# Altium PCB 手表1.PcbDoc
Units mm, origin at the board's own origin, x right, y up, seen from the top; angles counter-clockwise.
Board outline 35.6 x 38.85 mm, 2 copper layers (Top Layer, Bottom Layer); 53 components, 41 nets, 221 pads, 136 vias.
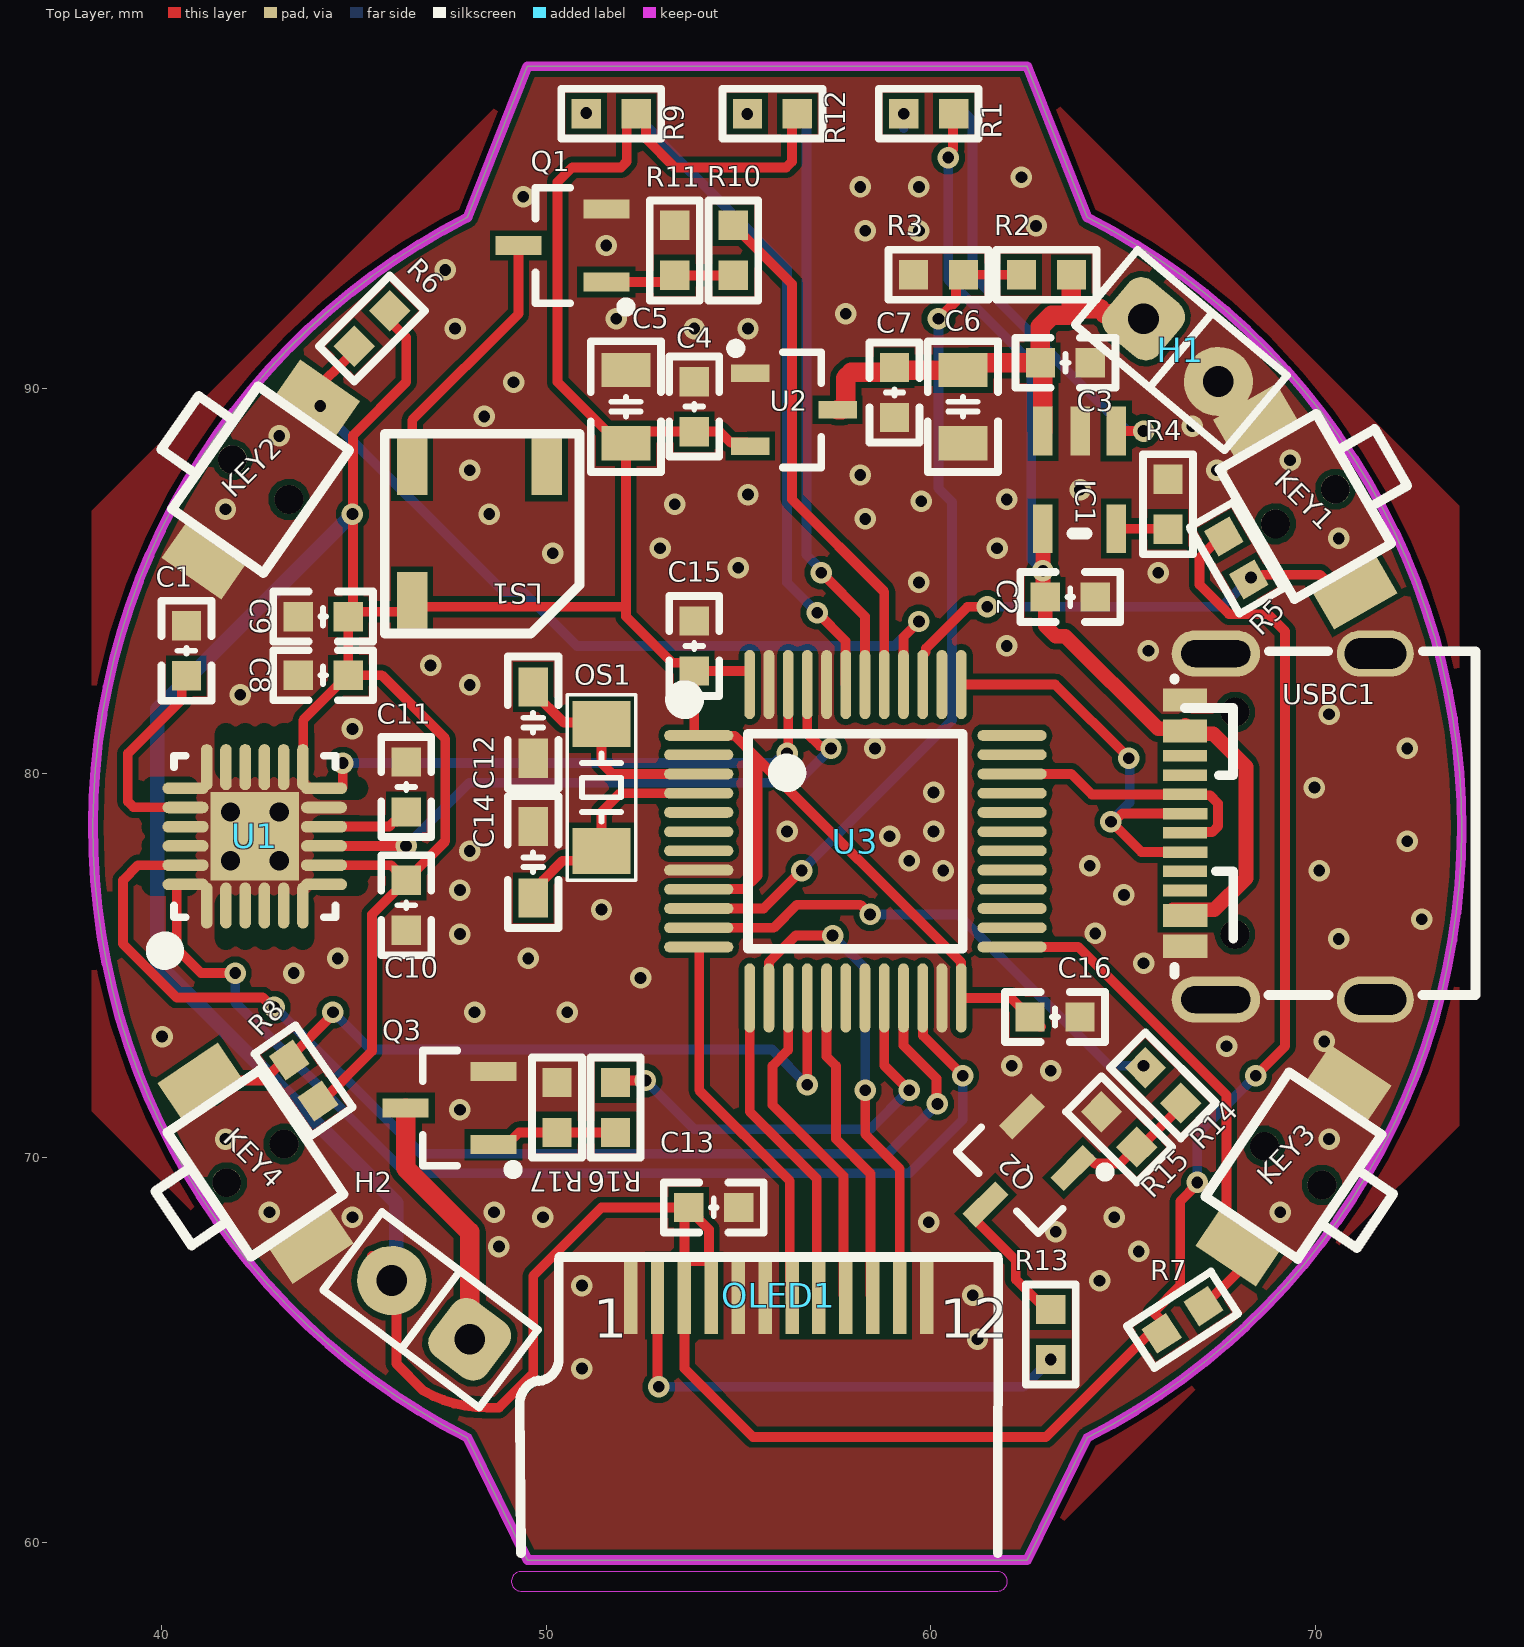
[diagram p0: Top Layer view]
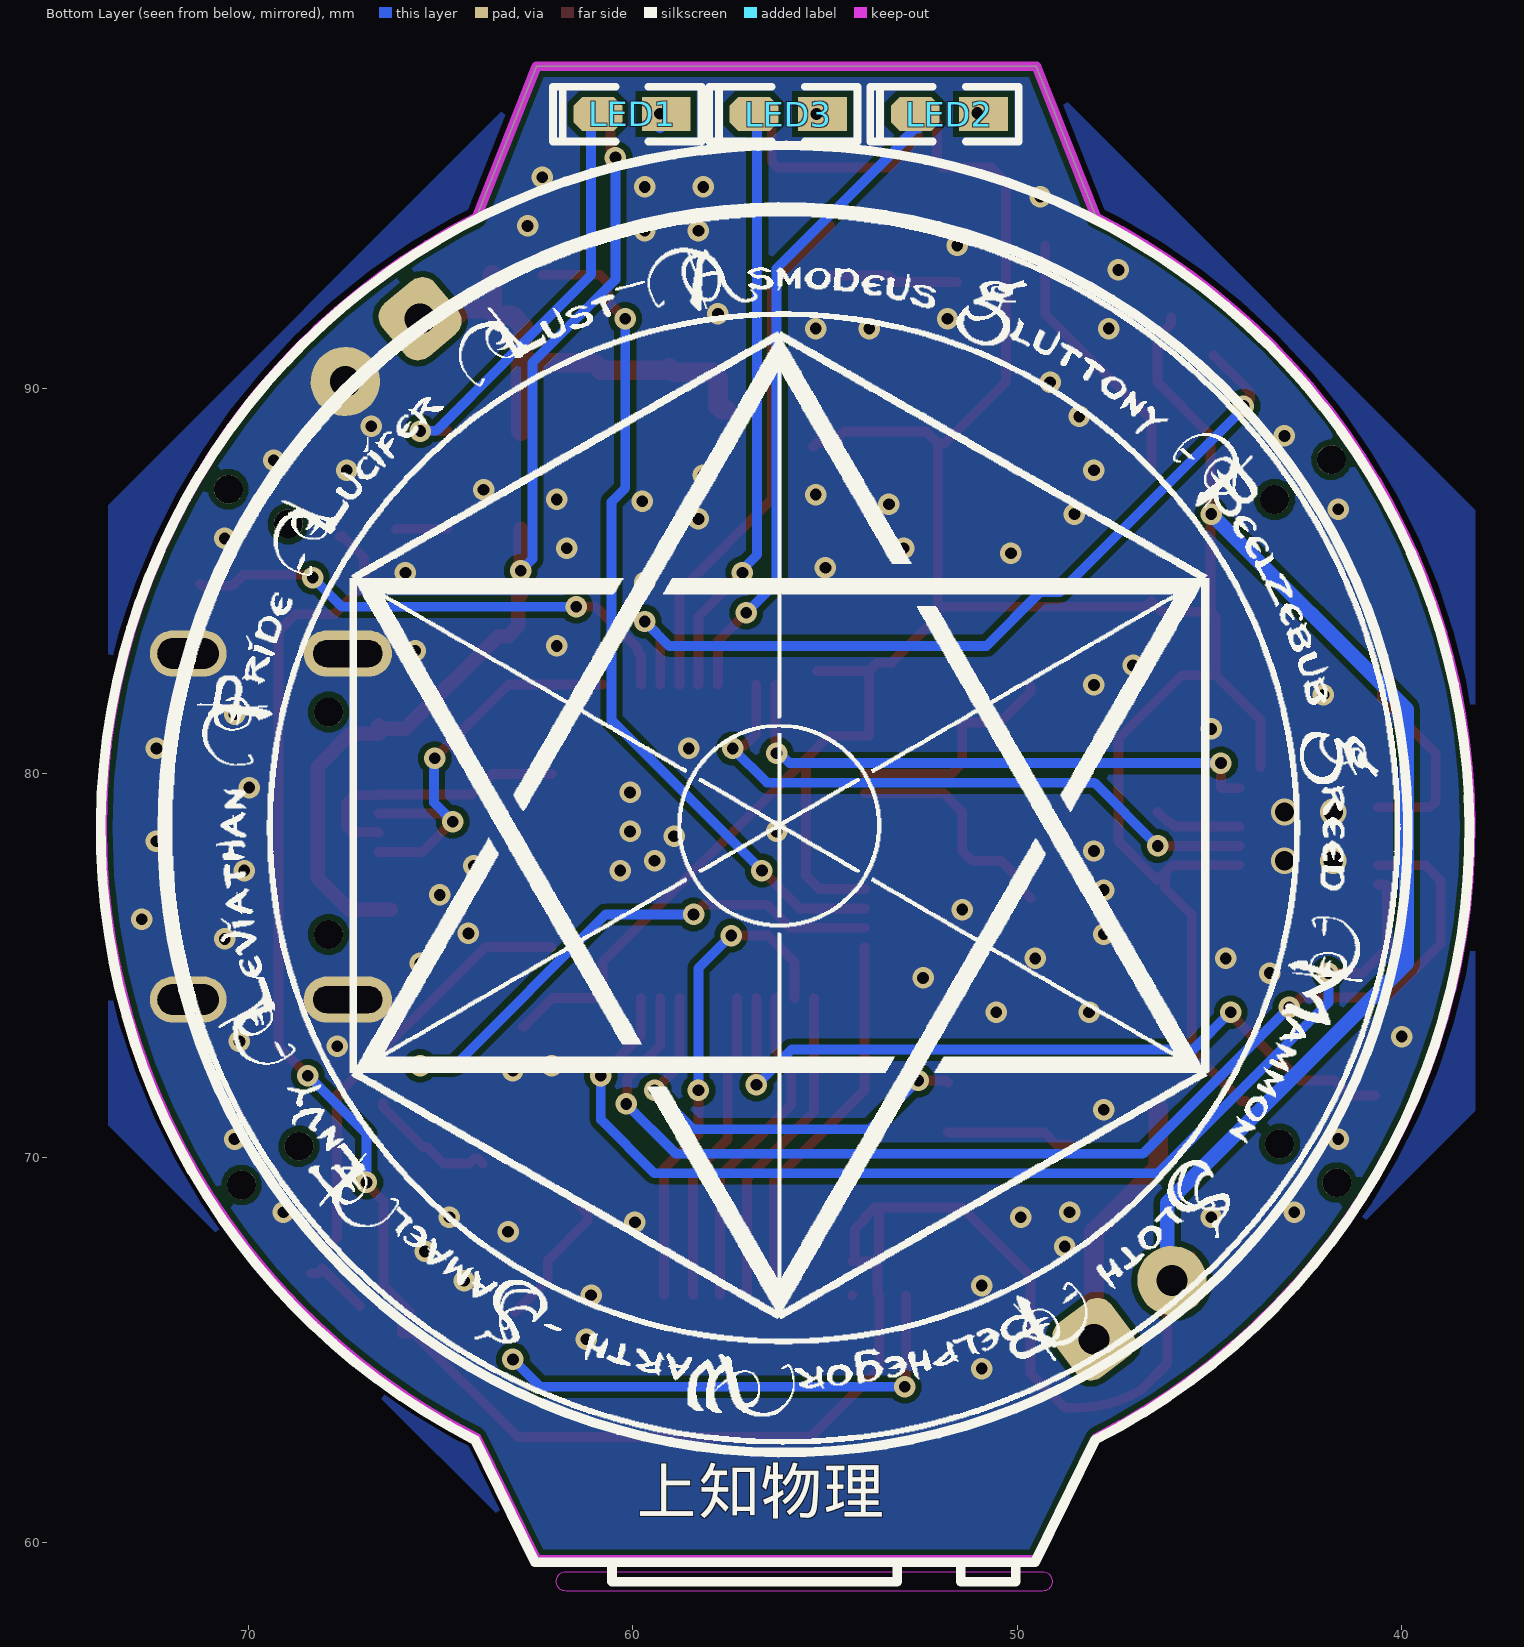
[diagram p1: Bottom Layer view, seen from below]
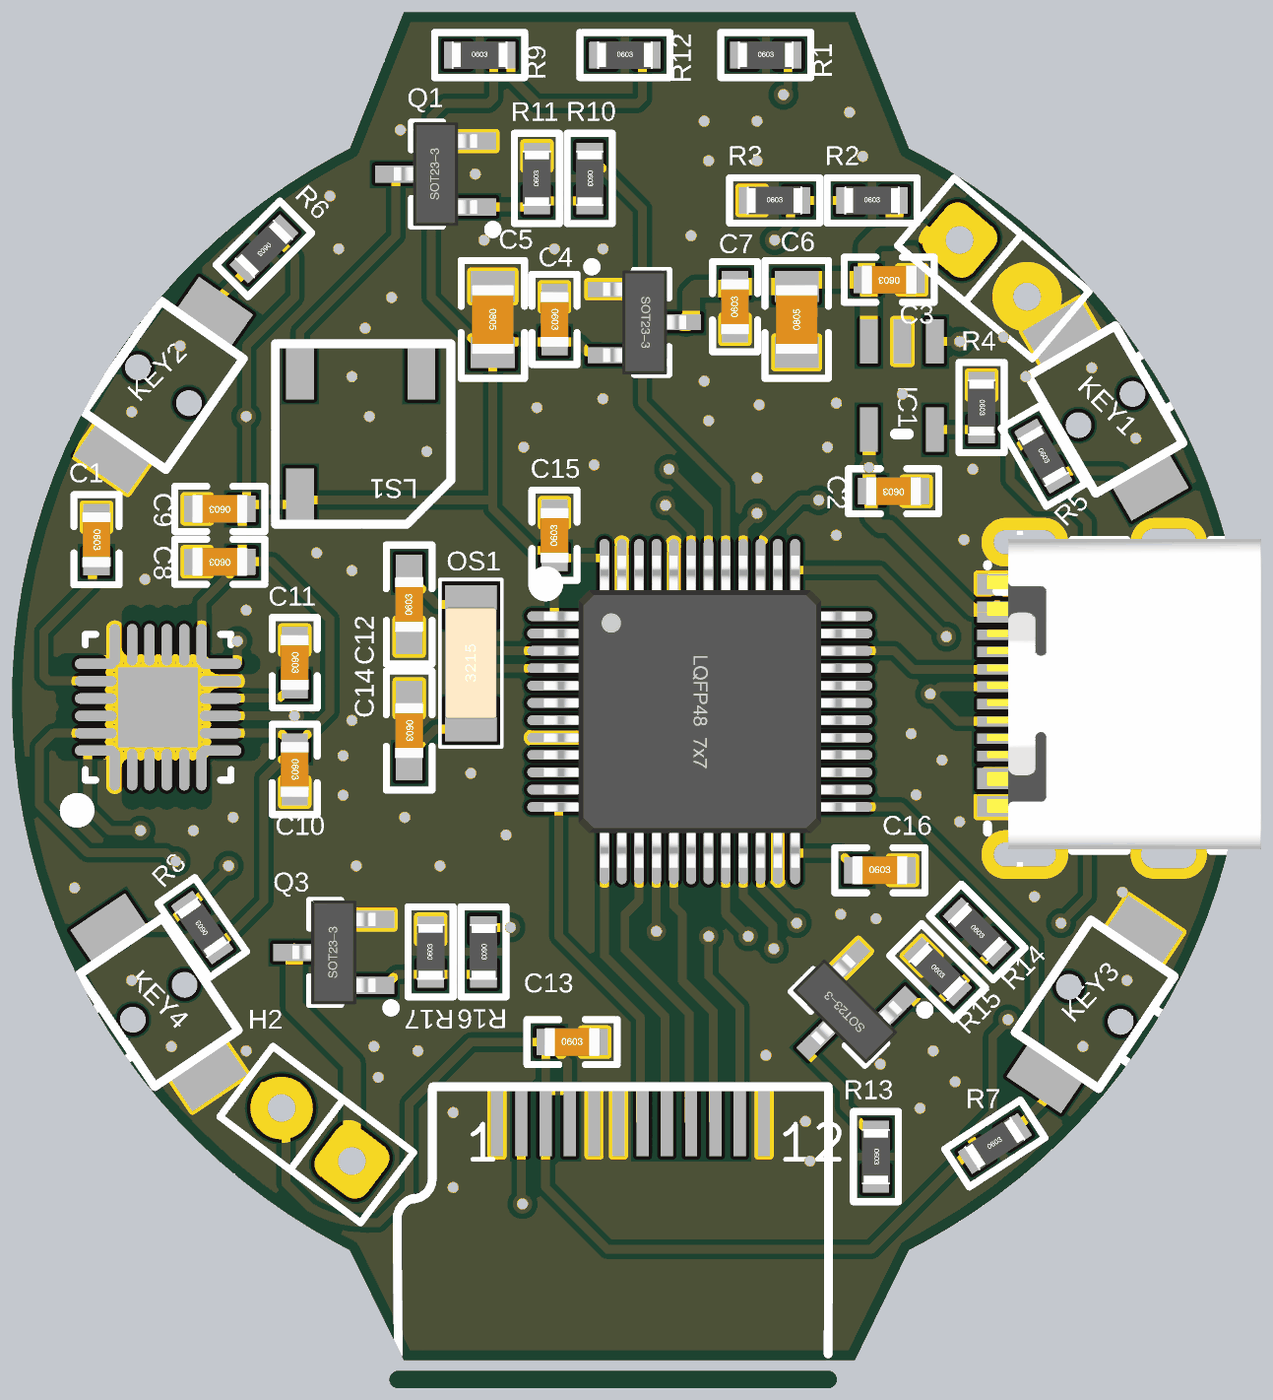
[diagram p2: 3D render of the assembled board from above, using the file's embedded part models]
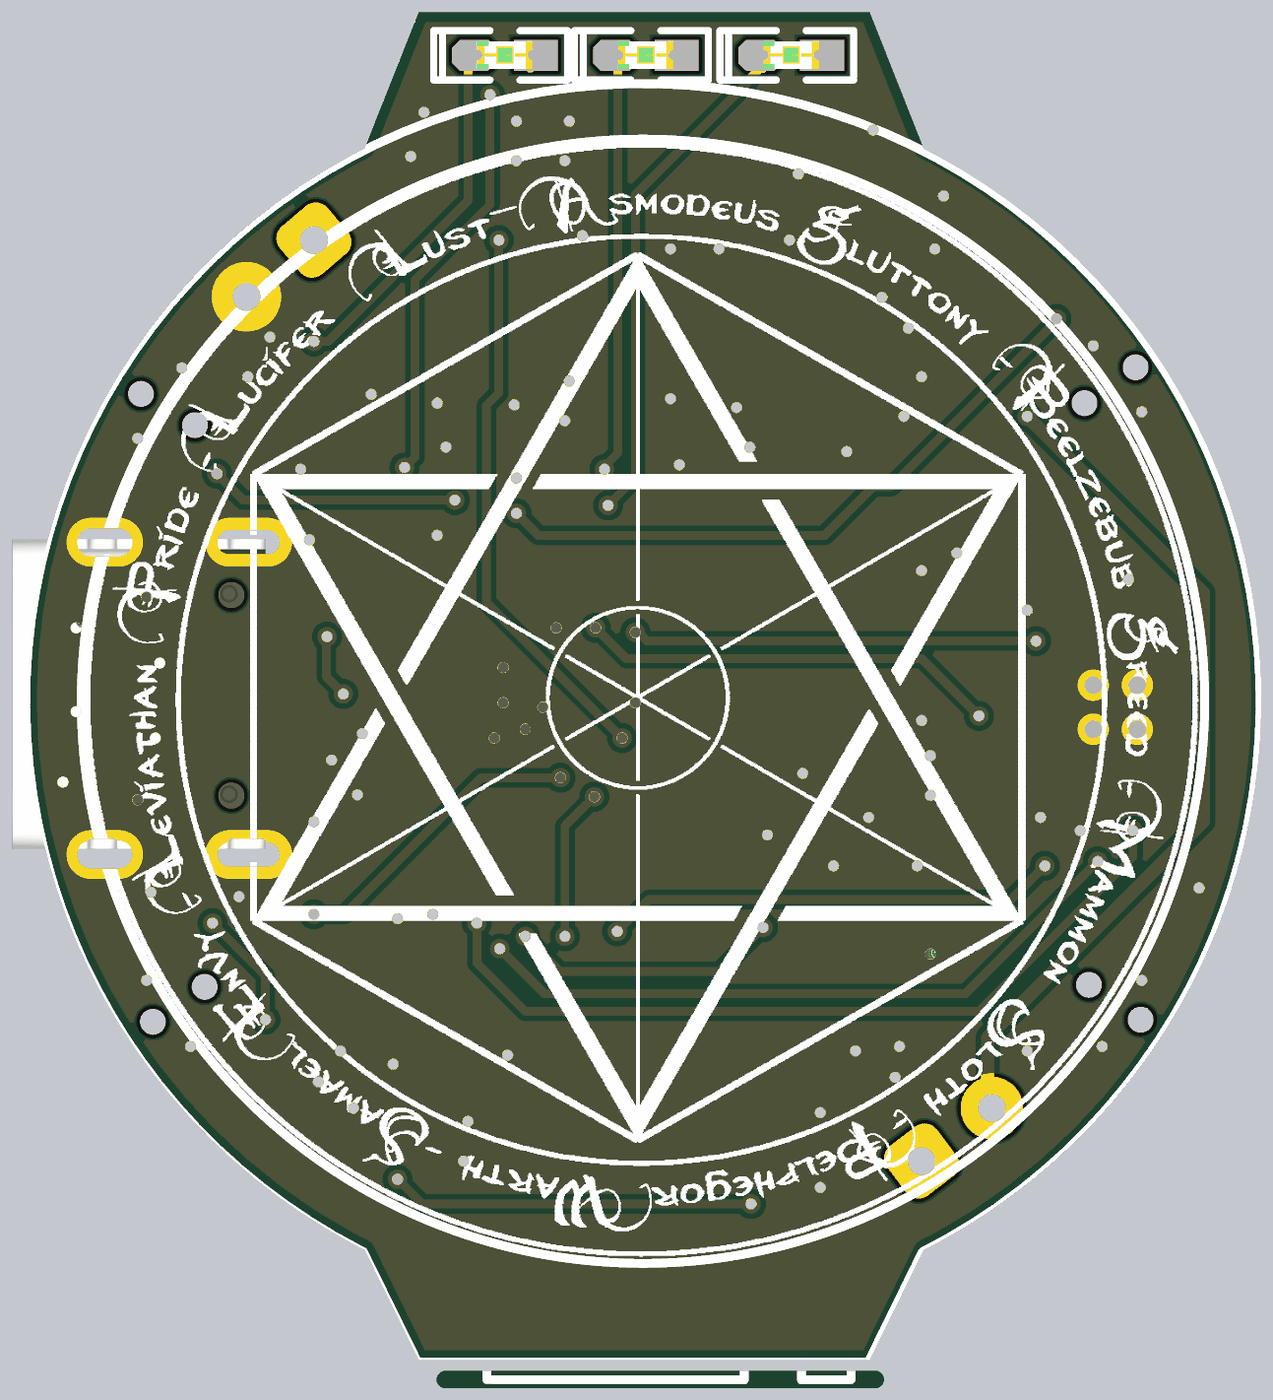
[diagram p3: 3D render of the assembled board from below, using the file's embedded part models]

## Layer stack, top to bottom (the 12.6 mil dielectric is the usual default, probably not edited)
Top Solder: solder mask 0.0102, Solder Resist, Dk 3.5
Top Layer: signal copper 0.0356
Dielectric 1: dielectric 0.32, FR-4, Dk 4.8
Bottom Layer: signal copper 0.0356
Bottom Solder: solder mask 0.0102, Solder Resist, Dk 3.5

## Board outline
47.947,62.717 cw(c56.007,78.588) 38.26,77.219 38.261,77.219 cw(c56.007,78.588) 47.947,94.458 49.502,98.383 49.507,98.388 62.507,98.388 62.512,98.373 64.067,94.458 64.087,94.448 cw(c56.007,78.588) 73.092,83.583 73.101,83.551 cw(c56.007,78.588) 64.067,62.718 62.507,59.538 49.507,59.538

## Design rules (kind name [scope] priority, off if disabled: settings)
Clearance [All] p1: gap=0.152 ignorepadtopadclearanceinfootprint=FALSE
PlaneConnect [All] p1: planeconnectstyle=Direct reliefexpansion=0.508 reliefentries=4 reliefconductorwidth=0.254 reliefairgap=0.254
PolygonConnect [All] p1: connectstyle=Direct reliefconductorwidth=0.254 reliefentries=4 polygonreliefangle="90 Angle" airgapwidth=0.254
RoutingVias [All] p1: holewidth=0.711 width=1.27 viastyle="Through Hole" minholewidth=0.711 minwidth=1.27 maxholewidth=0.711 maxwidth=1.27
SolderMaskExpansion [All] p1: expansion=0.102 istentingtop=FALSE
Width [All] p1: maxlimit=0.254 minlimit=0.203 preferedwidth=0.254
29 further rules are at their usual default settings.

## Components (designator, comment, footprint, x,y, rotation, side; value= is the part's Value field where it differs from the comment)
C1 "2.2uF" "C 0603_L" 40.64,83.185 r270 top
C2 "4.7u" "C 0603_L" 63.627,84.582 r180 top
C3 "10u" "C 0603_L" 63.5,90.678 r180 top
C4 "104" "C 0603_L" 53.848,89.535 r270 top
C5 "22u" "C 0805_L" 52.07,89.535 r270 top
C6 "22u" "C 0805_L" 60.833,89.535 r90 top
C7 "104" "C 0603_L" 59.055,89.901 r90 top
C8 "104" "C 0603_L" 44.196,82.55 r180 top
C9 "2.2uF" "C 0603_L" 44.196,84.074 r180 top
C10 "104" "C 0603_L" 46.355,76.566 r270 top
C11 "104" "C 0603_L" 46.355,79.644 r270 top
C12 "10P" "C 0603_M" 49.657,81.318 r90 top
C13 "104" "C 0603_L" 54.356,68.707 r0 top
C14 "10P" "C 0603_M" 49.657,77.686 r270 top
C15 "104" "C 0603_L" 53.848,83.312 r90 top
C16 "104" "C 0603_L" 63.231,73.66 r0 top
H1 "PAD2" PAD2-2.54 65.532,91.821 r320 top
H2 "PAD2" PAD2-2.54 48.006,65.278 r143 top
IC1 "TP4054" SOT-25 62.179,89.916 r0 top
KEY1 "微动按键" YD-3410小龟/微动开关 71.04,84.685 r120 top
KEY2 "微动按键" YD-3410小龟/微动开关 44.061,89.768 r235 top
KEY3 "微动按键" YD-3410小龟/微动开关 67.975,67.641 r56 top
KEY4 "微动按键" YD-3410小龟/微动开关 40.98,72.01 r304 top
LED1 "红色" "LED 0603R" 60.02,97.153 r0 bottom
LED2 "红色" "LED 0603R" 51.765,97.153 r0 bottom
LED3 "红色" "LED 0603R" 55.956,97.153 r0 bottom
LS1 "2~5V" "BEEP SMD 5*5*2" 48.26,86.233 r270 top
OLED1 "OLED裸屏" "圆形IPS LCD屏" 56.061,78.536 r180 bottom
OS1 "32.768KHz" "OSC 3215-2P" 51.435,79.629 r90 top
Q1 "SS8050" SOT23-3N 50.419,93.726 r90 top
Q2 "SS8050" SOT23-3N 62.23,69.596 r135 top
Q3 "SS8050" SOT23-3N 47.483,71.293 r90 top
R1 "1K" "R 0603_L" 59.944,97.155 r0 top
R2 "50K" "R 0603_L" 63.007,92.964 r0 top
R3 "150K" "R 0603_L" 60.198,92.964 r0 top
R4 "2K" "R 0603_L" 66.167,86.995 r270 top
R5 "10K" "R 0603_L" 67.945,85.598 r300 top
R6 "10K" "R 0603_L" 45.466,91.567 r225 top
R7 "10K" "R 0603_L" 66.548,65.786 r33 top
R8 "10K" "R 0603_L" 43.688,72.009 r125 top
R9 "2K" "R 0603_L" 51.689,97.155 r0 top
R10 "1K" "R 0603_L" 54.864,93.599 r270 top
R11 "10K" "R 0603_L" 53.34,93.599 r90 top
R12 "2K" "R 0603_L" 55.88,97.155 r0 top
R13 "10" "R 0603_L" 63.119,65.405 r270 top
R14 "1K" "R 0603_L" 66.04,71.882 r315 top
R15 "10K" "R 0603_L" 64.897,70.739 r315 top
R16 "1K" "R 0603_L" 51.801,71.308 r270 top
R17 "10K" "R 0603_L" 50.277,71.308 r90 top
U1 "MPU6050" QFN_24 42.418,78.359 r0 top
U2 "XC6206" SOT23-3L 56.45,89.451 r270 top
U3 "STM32F031C6" "LQFP48 7X7_N" 58.039,78.232 r270 top
USBC1 "TYPE-C 2.0 -16P" USB-C-SMD_TYPE-C-USB-5 69.088,78.613 r90 top

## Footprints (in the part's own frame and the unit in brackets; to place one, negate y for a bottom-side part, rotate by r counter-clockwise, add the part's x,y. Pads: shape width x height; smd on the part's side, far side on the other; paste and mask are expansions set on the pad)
"BEEP SMD 5*5*2" [mm] "贴片无源蜂鸣器"
  rect 1.5x0.8 smd: 1(1.75,-1.75) 2(-1.75,1.75) 3(-1.75,-1.75)
  silkscreen extent -2.6,-2.46 2.6,2.6
"C 0603_L" [mil] "无极性贴片电容                                       淘宝ID:黄晶宝石"
  rect 30x30 smd: 1(-25.59,0) 2(25.59,0)
  silkscreen extent -51,-26 51,26, body extent -31,-16 31,16, height 32
"C 0603_M" [mil] "无极性贴片电容                                淘宝ID:黄晶宝石"
  rect 40x30 smd: 1(-36.5,0) 2(36.5,0)
  silkscreen extent -68,-26 68,26, body extent -31,-16 31,16, height 32
"C 0805_L" [mil] "无极性贴片电容                                        淘宝ID:黄晶宝石"
  rect 35x50 smd: 1(-37.4,0) 2(37.4,0)
  silkscreen extent -67,-36 67,36, body extent -39,-24 39,24, height 20
"LED 0603R" [mil] "红色0603LED                                           淘宝ID:黄晶宝石"
  rect 50x35 smd: 1(-35,0.26)
  oct 50x35 smd: 2(35,0.26)
  silkscreen extent -71,-28 81,28, body extent -31,-16 31,16, height 24
"LQFP48 7X7_N" [mm] "48脚，体宽7x7mm，脚距0.5mm"
  oval 0.279x1.8 smd: 1(-2.75,-4.075) 2(-2.25,-4.075) 3(-1.75,-4.075) 4(-1.25,-4.075) 5(-0.75,-4.075) 6(-0.25,-4.075) 7(0.25,-4.075) 8(0.75,-4.075) 9(1.25,-4.075) 10(1.75,-4.075) 11(2.25,-4.075) 12(2.75,-4.075) 25(2.75,4.075) 26(2.25,4.075) 27(1.75,4.075) 28(1.25,4.075) 29(0.75,4.075) 30(0.25,4.075) 31(-0.25,4.075) 32(-0.75,4.075) 33(-1.25,4.075) 34(-1.75,4.075) 35(-2.25,4.075) 36(-2.75,4.075)
  oval 1.8x0.279 smd: 13(4.075,-2.75) 14(4.075,-2.25) 15(4.075,-1.75) 16(4.075,-1.25) 17(4.075,-0.75) 18(4.075,-0.25) 19(4.075,0.25) 20(4.075,0.75) 21(4.075,1.25) 22(4.075,1.75) 23(4.075,2.25) 24(4.075,2.75) 37(-4.075,2.75) 38(-4.075,2.25) 39(-4.075,1.75) 40(-4.075,1.25) 41(-4.075,0.75) 42(-4.075,0.25) 43(-4.075,-0.25) 44(-4.075,-0.75) 45(-4.075,-1.25) 46(-4.075,-1.75) 47(-4.075,-2.25) 48(-4.075,-2.75)
  silkscreen extent -3.93,-4.69 2.79,2.79, body extent -4.5,-4.5 4.5,4.5, height 1.45
"OSC 3215-2P" [mm] "3.2*1.5*0.6mm(长宽高)                      淘宝ID:黄晶宝石"
  rect 1.2x1.5 smd: 1(-1.65,0) 2(1.65,0)
  silkscreen extent -2.41,-0.89 2.41,0.89, body extent -1.6,-0.75 1.6,0.75, height 0.61
PAD2-2.54 [mm] "引线焊盘"
  rrect50% 1.8x1.8 hole 0.8: 1(0,0)
  round 1.8 hole 0.8: 2(2.54,0)
  silkscreen extent -1.27,-1.27 3.81,1.27
QFN_24 [mm]
  oval 0.3x1.2 smd: 1(-1.25,-1.8) 2(-0.75,-1.8) 3(-0.25,-1.8) 4(0.25,-1.8) 5(0.75,-1.8) 6(1.25,-1.8) 13(1.25,1.8) 14(0.75,1.8) 15(0.25,1.8) 16(-0.25,1.8) 17(-0.75,1.8) 18(-1.25,1.8)
  oval 1.2x0.3 smd: 7(1.8,-1.25) 8(1.8,-0.75) 9(1.8,-0.25) 10(1.8,0.25) 11(1.8,0.75) 12(1.8,1.25) 19(-1.8,1.25) 20(-1.8,0.75) 21(-1.8,0.25) 22(-1.8,-0.25) 23(-1.8,-0.75) 24(-1.8,-1.25)
  rect 2.3x2.3 smd: 18(0,0)
  silkscreen extent -2.59,-3.22 2.1,2.1, body extent -2.07,-2.07 2.07,2.07, height 1
"R 0603_L" [mil] "1/10W贴片电阻                 淘宝ID:黄晶宝石"
  rect 30x30 smd: 1(-25.59,0) 2(25.59,0)
  silkscreen extent -51,-26 51,26, body extent -31,-16 32,16, height 16
SOT23-3L [mm] "3x1.3x1mm(长宽高)    封装库来自淘宝卖家 ID：黄晶宝石"
  rect 0.45x1 smd: 1(-0.95,-1.143) 2(0.95,-1.143) 3(0,1.125)
  silkscreen extent -1.72,-1.65 1.5,0.7, body extent -1.5,-1.2 1.5,1.2, height 1.05
SOT23-3N [mm] "3x1.3x1mm(长宽高)    封装库来自淘宝卖家 ID：黄晶宝石"
  rect 0.5x1.2 smd: 1(-0.95,-1.143) 2(0.95,-1.143) 3(0,1.143)
  silkscreen extent -1.72,-1.78 1.5,0.7, body extent -1.5,-1.2 1.5,1.2, height 1.05
SOT-25 [mil] "封装库来自淘宝卖家 ID：黄晶宝石"
  rect 20x50 smd: 1(104,-40) 2(67,-40) 3(29,-40) 4(29,-140) 5(104,-140)
  silkscreen extent 59,-145 74,-145
USB-C-SMD_TYPE-C-USB-5 [mm]
  oval 1.2x2 hole 0.8 slot 1.6 at 90 deg: 0(-4.5,-2.475) 0(4.5,-2.475)
  oval 1.2x2.3 hole 0.7 slot 1.8 at 90 deg: 0(-4.5,1.675) 0(4.5,1.675)
  rect 0.3x1.15 smd: A1(-3.263,2.473) A4(-2.462,2.471) A5(-1.162,2.475) A6(-0.162,2.475) A7(0.337,2.473) A9(2.638,2.475) A12(3.438,2.475) B1(3.138,2.475) B4(2.337,2.475) B5(1.838,2.475) B6(0.838,2.475) B7(-0.663,2.473) B9(-2.162,2.471) B12(-2.963,2.473)
  rect 0.3x1.148 smd: A8(-1.663,2.475) B8(1.337,2.475)
  round 0.75 hole 0.75 unplated: ""(-2.803,1.175) ""(2.978,1.175)
  silkscreen extent -4.38,-5.08 4.56,2.75, body extent -4.34,-5.14 4.6,2.76, height 3.25
YD-3410小龟/微动开关 [mm] "YD-3410小龟/微动开关侧躺"
  rect 1.1x1.9 smd: 1(0,0) 2(5.2,0)
  round 0.75 hole 0.75 unplated: ""(2.6,0.9) ""(2.6,-0.9)
  silkscreen extent 0.65,-2.57 4.55,1.45
"圆形IPS LCD屏" [mm] "中景园 圆形IPS LCD屏"
  rect 0.35x2 smd far side: 1(3.87,-12.115) 2(3.17,-12.115) 3(2.47,-12.115) 4(1.77,-12.115) 5(1.07,-12.115) 6(0.37,-12.115) 7(-0.33,-12.115) 8(-1.03,-12.115) 9(-1.73,-12.115) 10(-2.43,-12.115) 11(-3.13,-12.115) 12(-3.83,-12.115)
  Keep-Out Layer board cut-out: -5.68,-19.305 6.72,-19.305 6.829,-19.33 6.916,-19.399 6.964,-19.499 6.964,-19.611 6.916,-19.711 6.829,-19.78 6.72,-19.805 6.72,-19.805 -5.68,-19.805 -5.788,-19.78 -5.875,-19.711 -5.924,-19.611 -5.924,-19.499 -5.875,-19.399 -5.788,-19.33 -5.68,-19.305
  silkscreen extent -17.78,-19.56 17.82,17.8

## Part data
C1 C2 C3 C4 C5 C6 C7 C8 C9 C10 C11 C12 C13 C14 C15 C16: library part C, "贴片电容"
H1 H2: "引线焊盘"
IC1: "锂电池充电管理"
KEY1 KEY2 KEY3 KEY4: library part YD-3410小龟, "YD-3410小龟侧躺"
LED1 LED2 LED3: library part LED-SMD, "贴片LED"
LS1: library part BEEP_SMD, "贴片无源蜂鸣器"
OLED1: library part "圆形IPS LCD屏", "圆形IPS LCD屏"
OS1: library part XTAL-2P, "2脚无源脚晶振"
Q1 Q2 Q3: library part 8050-SMD, "高频放大-NPN型"
R1 R2 R3 R4 R5 R6 R7 R8 R9 R10 R11 R12 R13 R14 R15 R16 R17: library part R, "贴片电阻"
U1: "三轴加速度+三轴陀螺仪"
U2: "小体积线性稳压器"
U3: library part STM32F030C6, "32位STM单片机"
USBC1: library part "USB2.0 Type-C 16Pin母座", "USB2.0 Type-C 母座 16Pin", BOM_Manufacturer=LCSC, BOM_Manufacturer Part=-

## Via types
v1: diameter 0.559, hole 0.305, Top Layer to Bottom Layer, tented both sides, 132 vias
v2: diameter 0.7, hole 0.5, Top Layer to Bottom Layer, 4 vias

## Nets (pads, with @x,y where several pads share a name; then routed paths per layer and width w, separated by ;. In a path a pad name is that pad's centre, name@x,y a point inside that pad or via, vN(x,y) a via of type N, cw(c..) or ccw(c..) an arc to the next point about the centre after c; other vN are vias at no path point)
3V3: C4.2 C5.2 C8.1 C9.1 C10.1 C13.1 C15.1 C16.1 H2.2 LS1.1 OLED1.3 OLED1.4 R5.1 R6.1 R7.1 R8.1 R9.2 R12.2 U1.8 U1.13 U2.2 U3.1 U3.9 U3.24 U3.48 | length 168.9
  Top Layer w0.254: U1.13 43.677,80.168 43.677,81.381 C8.1 ; R8.1 44.172,71.477 45.466,72.771 45.466,76.327 46.159,77.02 C10.1@46.159,77.412 ; U1.8 45.962,77.609 C10.1@46.159,77.412 ; H2.2@45.469,67.442 45.466,67.438 45.466,66.807 H2.2@45.682,66.591 ; H2.2 46.101,66.683 46.101,64.643 46.781,63.963 46.805,63.939 ccw(c48.451,66.808) 48.451,63.5 48.768,63.5 49.657,64.389 49.657,66.929 51.435,68.707 C13.1 53.594,68.595 53.594,67.443 ; R6.1@46.004,91.851 46.004,91.686 46.355,91.335 46.355,90.17 44.973,88.788 C9.1@44.973,84.201 ; OLED1.3@53.639,67.183 53.639,66.469 OLED1.3 53.591,64.519 55.372,62.738 62.992,62.738 65.686,65.432 R7.1 66.003,65.764 65.786,65.981 66.484,66.679 66.484,68.867 66.929,69.312 v1(66.929,69.357) ; 53.639,67.429 53.639,67.31 OLED1.3@53.65,67.31 ; OLED1.3@53.642,67.183 53.642,67.302 OLED1.3@53.65,67.31 ; C13.1@53.729,68.683 53.96,68.453 53.96,68.406 54.229,68.137 OLED1.4@54.229,67.31 ; U3.9 53.968,76.987 55.143,76.987 55.499,77.343 55.499,80.371 ; OLED1.4@54.288,66.424 OLED1.4 ; OLED1.4@54.291,67.31 OLED1.4@54.229,67.31 ; U3.48@55.207,82.662 C15.1 ; U2.2 55.209,88.599 54.794,88.599 54.508,88.885 C4.2 52.37,88.885 C5.2 ; R12.2@56.624,97.031 56.518,97.031 56.388,96.901 56.388,95.907 56.239,95.758 53.34,95.758 52.593,96.505 52.593,96.901 52.537,96.957 52.141,96.957 52.092,96.908 52.092,95.907 51.943,95.758 50.673,95.758 50.292,95.377 50.292,90.172 51.879,88.585 C5.2 ; C16.1@62.865,73.406 62.835,73.406 C16.1 62.084,74.157 U3.24 60.784,74.161 60.784,75.086 55.499,80.371 ; R5.1 67.545,86.161 66.989,85.604 66.989,84.903 67.755,84.137 68.771,84.137 69.215,83.693 69.215,72.898 v1(68.453,72.136) ; C8.1 C9.1 C9.1@44.973,84.201 ; C8.1 45.72,82.55 47.371,80.899 47.371,78.232 C10.1 C10.1@46.159,77.412 ; C9.1@44.973,84.201 46.237,84.201 46.51,84.474 LS1.1 46.665,84.328 52.07,84.328 ; 52.07,84.328 52.07,84.074 53.269,82.875 53.635,82.875 C15.1 ; 52.07,84.328 52.07,84.582 C5.2 ; OLED1.3@53.65,67.31 OLED1.4@54.229,67.31 ; C15.1 53.848,80.994 53.86,80.982 U3.1 53.968,80.977 54.893,80.977 55.499,80.371
  Bottom Layer w0.254: v1(66.929,69.357) 66.929,70.612 v1(68.453,72.136)
  Bottom Layer w0.381: v1(44.958,86.741) 39.878,81.661 39.878,75.057 46.101,68.834 46.101,66.93 H2.2
+5: C2.2 IC1.4 R1.2 USBC1.A4 USBC1.A9 USBC1.B4 USBC1.B9 | length 27.4
  Top Layer w0.254: v1(60.452,96.012) 60.452,96.094 60.579,96.221 60.579,97.013 R1.2@60.594,97.028
  Top Layer w0.381: IC1.4 v1(62.916,85.268) 62.916,84.643 C2.2 62.977,83.835 63.246,83.566 63.5,83.566 65.913,81.153 USBC1.A9@66.486,81.153 ; USBC1.B9@66.294,76.451 USBC1.B9 67.376,76.451 68.199,77.274 68.199,80.171 67.344,81.026 66.613,81.026 USBC1.A9@66.486,81.153 ; USBC1.A9 66.515,81.153 USBC1.A9@66.486,81.153
  Bottom Layer w0.254: v1(60.452,96.012) 60.452,92.837 62.611,90.678 62.611,85.573 v1(62.916,85.268)
AD0: U1.9 U3.45 | length 16.3
  Top Layer w0.254: U1.9 v1(46.351,78.109) v1@46.355,78.105 ; U3.45 56.789,81.026 57.112,80.703 57.346,80.703 v1(57.404,80.645)
  Bottom Layer w0.254: v1(46.351,78.109) 47.998,79.756 56.515,79.756 v1(57.404,80.645)
ADC: R2.1 R3.2 U3.10 | length 22.1
  Top Layer w0.254: U3.10 55.654,76.482 v1(56.642,77.47) ; v1(60.198,91.821) 60.653,92.276 60.653,92.769 R3.2 R2.1
  Bottom Layer w0.254: v1(56.642,77.47) 60.554,81.382 60.554,87.055 60.198,87.411 v1(60.198,91.821)
BEEP: R10.1 U3.41 | length 13.6
  Top Layer w0.254: R10.1 56.388,92.725 56.388,87.122 58.789,84.721 U3.41
BLK: R14.1 U3.11 | length 13.6
  Top Layer w0.254: U3.11 55.916,75.982 56.515,76.581 58.166,76.581 v1(58.42,76.327)
  Bottom Layer w0.254: v1(58.42,76.327) 60.706,76.327 64.643,72.39 v1(65.532,72.39)
CS: OLED1.8 U3.13 | length 8.5
  Top Layer w0.254: U3.13 55.289,71.203 57.032,69.46 OLED1.8@57.032,66.421
DC: OLED1.7 U3.12 | length 10
  Top Layer w0.254: U3.12 53.975,75.471 53.975,71.755 56.332,69.398 OLED1.7@56.332,66.421
GND: C1.1 C2.1 C3.1 C4.1 C5.1 C6.1 C7.1 C8.2 C9.2 C10.2 C11.1 C12.1 C13.2 C14.1 C15.2 C16.2 H1.2 IC1.2 KEY1.2 KEY2.2 KEY3.2 KEY4.2 OLED1.1 OLED1.5 OLED1.6 OLED1.12 Q1.2 Q2.2 Q3.2 R3.1 R4.1 R11.2 R15.1 R17.2 U1.1 U1.11 U1.18 U2.1 U3.8 U3.23 U3.44 U3.47 USBC1.0 USBC1.A1 USBC1.A12 USBC1.B1 USBC1.B12
  other v1: 50.927,64.516 61.214,65.278 61.087,66.421 50.927,66.675 64.389,66.802 65.405,67.564 48.768,67.691 63.246,68.072 59.944,68.326 44.958,68.453 49.911,68.453 64.77,68.453 42.799,68.58 48.641,68.58 69.088,68.58 41.656,70.485 70.358,70.485 47.752,71.247 63.119,72.263 62.103,72.39 67.691,72.898 70.231,73.025 40.005,73.152 48.133,73.787 50.546,73.787 52.451,74.676 43.434,74.803 65.532,75.057 44.577,75.184 49.53,75.184 70.612,75.692 47.752,75.819 64.276,75.833 72.771,76.2 51.435,76.454 65.024,76.835 47.752,76.962 60.325,77.47 70.104,77.47 64.135,77.597 59.436,77.724 48.006,77.978 72.39,78.232 58.928,78.359 56.261,78.486 60.071,78.486 60.071,79.502 69.977,79.629 58.547,80.645 72.39,80.645 44.958,81.153 70.358,81.534 42.037,82.042 48.006,82.296 46.99,82.804 65.659,83.185 61.976,83.312 59.69,84.963 65.913,85.217 54.991,85.344 50.165,85.725 52.959,85.852 61.722,85.852 70.612,86.106 58.293,86.614 48.514,86.741 41.656,86.868 53.34,86.995 59.753,87.073 61.976,87.122 55.245,87.249 63.881,87.376 58.166,87.757 48.006,87.884 67.437,87.884 69.342,88.138 43.053,88.773 66.802,89.027 48.387,89.281 49.149,90.17 47.625,91.567 53.848,91.567 55.245,91.567 51.816,91.821 57.785,91.948 47.371,93.091 51.562,93.726 58.293,94.107 59.69,94.107 62.738,94.234 49.403,94.996 58.166,95.25 59.69,95.25 62.357,95.504
  other v2: 41.783,77.724 43.053,77.724 41.783,78.994 43.053,78.994
INT: U1.12 U3.46 | length 14.6
  Top Layer w0.254: U1.12 44.683,79.609 44.704,79.63 v1(44.704,80.264) ; v1(56.261,80.518) 56.289,80.546 U3.46
  Bottom Layer w0.254: v1(44.704,80.264) 55.925,80.264 56.179,80.518 v1(56.261,80.518)
KEY1: KEY1.1 R5.2 U3.39 | length 13.1
  Top Layer w0.254: U3.39 59.789,83.075 59.87,83.155 59.87,83.241 60.957,84.328 v1(61.468,84.328) ; R5.2 v1(68.326,85.09) R5.2@68.38,85.035 ; R5.2@68.634,85.162 70.131,85.162 70.416,84.877 71.208,84.877 KEY1.1@71.26,84.928
  Bottom Layer w0.254: v1(61.468,84.328) 67.564,84.328 v1(68.326,85.09)
KEY2: KEY2.1 R6.2 U3.40 | length 21.8
  Top Layer w0.254: KEY2.1@43.949,89.725 43.949,89.923 R6.2@44.894,90.869 ; U3.40 59.289,83.546 v1(59.69,83.947)
  Bottom Layer w0.254: v1@44.086,89.518 48.895,84.709 49.403,84.709 50.8,83.312 59.055,83.312 v1(59.69,83.947)
  other v1: 44.119,89.551
KEY3: KEY3.1 R7.2 U3.25 | length 12.9
  Top Layer w0.254: U3.25 63.837,75.482 67.691,71.628 67.691,67.924 KEY3.1 ; R7.2 KEY3.1@68.077,67.124 ; KEY3.1@68.188,66.997 KEY3.1@68.375,66.997
KEY4: KEY4.1 R8.2 U3.16 | length 19.9
  Top Layer w0.254: KEY4.1@40.694,71.62 41.343,71.62 41.732,72.009 42.641,72.009 43.047,72.414 R8.2@43.188,72.414 ; R8.2 43.315,72.597 44.45,73.732 v1(44.45,73.787) ; v1(56.784,71.897) v1(56.787,71.9) 56.787,74.154 U3.16
  Bottom Layer w0.254: v1(44.45,73.787) 45.424,72.813 55.868,72.813 v1(56.784,71.897)
LCDK: OLED1.2 R13.2 | length 12.9
  Top Layer w0.254: OLED1.2 52.891,64.076 v1(52.925,64.042) v1@52.959,64.008
  Bottom Layer w0.254: v1(52.925,64.042) 62.406,64.042 v1(63.119,64.755)
LED1: LED3.2 U3.42 | length 15.1
  Top Layer w0.254: v1(57.15,85.217) 58.289,84.078 U3.42
  Bottom Layer w0.254: LED3.2@56.769,96.767 56.769,85.68 57.15,85.299 v1(57.15,85.217)
LED2: LED2.2 U3.43 | length 16.7
  Top Layer w0.254: v1(57.049,84.175) 57.784,83.44 57.784,82.312 U3.43
  Bottom Layer w0.254: LED2.2@52.578,96.767 52.663,96.767 52.938,96.493 52.938,96.45 56.261,93.127 56.261,84.963 v1@57.105,84.119
MOTOR: R16.1 U3.20 | length 11.3
  Top Layer w0.254: R16.1 51.851,72.009 v1(52.578,72.009) ; U3.20 58.789,72.402 v1(59.436,71.755)
  Bottom Layer w0.254: v1(52.578,72.009) 53.848,70.739 58.42,70.739 v1(59.436,71.755)
NetC1_2: C1.2 U1.20 | length 5.5
  Top Layer w0.254: U1.20 40.609,79.118 39.265,79.118 39.116,79.267 39.116,80.518 40.52,81.922 40.52,82.415 C1.2
NetC11_2: C11.2 U1.10 | length 2.3
  Top Layer w0.254: U1.10 44.227,78.618 45.915,78.618 46.038,78.74 46.101,78.74 C11.2
NetH2_1: H2.1 Q3.3 | length 6.2
  Top Layer w0.508: Q3.3 46.34,69.738 48.006,68.072 H2.1@48.006,65.759
NetIC1_1: IC1.1 LED1.2 | length 11.1
  Top Layer w0.254: IC1.1 v1(65.532,88.9)
  Bottom Layer w0.254: LED1.2 61.087,96.968 61.087,92.964 63.246,90.805 63.246,90.773 65.113,88.907 65.525,88.907 v1(65.532,88.9)
NetIC1_5: IC1.5 R4.2 | length 1.4
  Top Layer w0.254: IC1.5 66.152,86.36 R4.2
NetLED1_1: LED1.1 R1.1 | length 0.4
  Bottom Layer w0.254: LED1.1 59.294,96.984 LED1.1@59.294,96.774
  other v1: 59.294,97.155
NetLED2_1: LED2.1 R9.1 | length 0.2
  Top Layer w0.254: R9.1@51.019,97.148 51.032,97.148 R9.1 v1(51.039,97.172)
  Bottom Layer w0.254: LED2.1 50.938,97.146 LED2.1@51.039,97.045
NetLED3_1: LED3.1 R12.1 | length 0.2
  Top Layer w0.254: v1(55.223,97.148) R12.1
  Bottom Layer w0.254: LED3.1@55.223,97.021 LED3.1@55.23,97.021 ; LED3.1@55.23,97.021 55.23,97.11 LED3.1@55.23,97.021
NetLS1_3: LS1.3 Q1.3 | length 6.9
  Top Layer w0.254: LS1.3 46.51,89.182 49.276,91.948 Q1.3
NetQ1_1: Q1.1 R10.2 R11.1 | length 3.4
  Top Layer w0.254: Q1.1 53.167,92.776 R11.1 R10.2
NetQ2_1: Q2.1 R14.2 R15.2 | length 3.4
  Top Layer w0.254: Q2.1@63.903,69.85 64.033,69.98 64.131,69.98 64.261,69.85 64.919,69.85 65.348,70.279 65.453,70.279 66.5,71.326 R14.2
NetQ2_3: Q2.3 R13.1 | length 3.7
  Top Layer w0.254: Q2.3 61.174,68.54 61.174,68.366 62.21,67.331 62.21,66.837 R13.1@63.055,65.992
NetQ3_1: Q3.1 R16.2 R17.1 | length 3.3
  Top Layer w0.254: Q3.1 48.976,70.343 49.291,70.658 R17.1 R16.2
OSC32IN: C12.2 OS1.2 U3.3 | length 5.9
  Top Layer w0.254: C12.2 49.657,82.118 50.453,81.322 51.392,81.322 OS1.2 51.435,80.264 51.717,79.982 U3.3
OSC32OUT: C14.2 OS1.1 U3.4 | length 6.1
  Top Layer w0.254: C14.2 49.911,77.013 49.911,77.216 50.419,77.724 51.18,77.724 OS1.1 51.435,78.994 51.923,79.482 U3.4
RES: OLED1.11 U3.14 | length 13
  Top Layer w0.254: U3.14 55.794,74.161 55.794,75.086 56.487,75.779 v1(57.444,75.779) ; v1(58.293,71.755) 58.293,70.612 59.191,69.714 OLED1.11
  Bottom Layer w0.254: v1(57.444,75.779) 58.293,74.93 v1(58.293,71.755)
SCL: U1.23 U3.21 | length 30.5
  Top Layer w0.254: U1.23 39.382,77.609 38.989,77.216 38.989,75.565 40.386,74.168 42.625,74.168 42.879,73.914 v1(42.926,73.914) ; U3.21 59.289,72.918 60.147,72.06 60.147,71.425 v1(60.173,71.399)
  Bottom Layer w0.254: v1(42.926,73.914) 44.657,72.183 46.736,70.104 58.877,70.104 v1(60.173,71.399)
SDA: U1.24 U3.22 | length 29.4
  Top Layer w0.254: U1.24 40.407,77.109 40.386,77.088 40.386,75.438 41.021,74.803 v1(41.91,74.803) ; U3.22 59.794,74.152 59.794,73.175 v1(60.833,72.136)
  Bottom Layer w0.254: v1(41.91,74.803) 41.91,74.041 46.355,69.596 59.436,69.596 60.833,70.993 v1(60.833,72.136)
SPI_SCL: OLED1.9 U3.15 | length 8.7
  Top Layer w0.254: U3.15 56.289,72.799 55.88,72.39 55.88,71.374 57.732,69.522 OLED1.9@57.732,66.421
SPI_SDA: OLED1.10 U3.17 | length 8.2
  Top Layer w0.254: U3.17 57.289,73.373 57.289,72.632 57.531,72.39 57.531,70.485 58.432,69.584 OLED1.10@58.432,66.421
SWCLK: U3.37 USBC1.A7 USBC1.B7 | length 11.3
  Top Layer w0.254: U3.37 63.235,82.307 v1(65.151,80.391) ; USBC1.B7 65.474,77.95 v1(64.684,78.74) 64.767,78.74 64.977,78.95 USBC1.A7
  Bottom Layer w0.254: v1(64.684,78.74) 64.684,78.752 65.172,79.239 65.172,80.37 v1(65.151,80.391)
SWDIO: U3.34 USBC1.A6 USBC1.B6 | length 7.2
  Top Layer w0.254: U3.34 63.655,79.982 64.186,79.451 USBC1.B6 66.636,79.428 67.258,79.428 67.469,79.216 67.469,78.622 67.32,78.474 66.636,78.474 USBC1.A6
VBAT: C3.2 C6.2 C7.2 H1.1 IC1.3 R2.2 U2.3 | length 12.9
  Top Layer w0.508: U2.3 57.687,89.451 57.785,89.549 57.785,90.275 57.934,90.424 58.928,90.424 C7.2 59.121,90.485 C6.2 61.026,90.678 C3.2 ; IC1.3 62.916,90.612 C3.2 ; 63.657,92.075 64.404,92.075 64.528,91.951 65.402,91.951 H1.1 ; R2.2 63.657,92.329 63.657,92.01 63.56,91.913 63.148,91.913 62.85,91.615 C3.2
pads on no net: KEY1. KEY2. KEY3. KEY4. LS1.2 U1.2 U1.3 U1.4 U1.5 U1.6 U1.7 U1.14 U1.15 U1.16 U1.17 U1.19 U1.21 U1.22 U3.2 U3.5 U3.6 U3.7 U3.18 U3.19 U3.26 U3.27 U3.28 U3.29 U3.30 U3.31 U3.32 U3.33 U3.35 U3.36 U3.38 USBC1. USBC1.A5 USBC1.A8 USBC1.B5 USBC1.B8

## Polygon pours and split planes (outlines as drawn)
GND on Bottom Layer "NONET_L-01_P-001" (solid, pour order 3): 49.517,98.276 62.344,98.276 73.647,86.973 73.647,70.844 62.471,59.668 49.644,59.668 38.087,71.225 38.087,86.846
GND on Top Layer "NONET_L-01_P-001" (solid, pour order 2): 49.607,98.264 62.434,98.264 73.737,86.961 73.737,70.832 62.561,59.656 49.734,59.656 38.177,71.213 38.177,86.834

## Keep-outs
Keep-Out Layer:
  lines w0.254: 38.26,77.219 ccw(c56.007,78.588) 47.947,62.717 49.507,59.538 62.507,59.538 64.067,62.718 ccw(c56.007,78.588) 73.101,83.551 ; 38.261,77.219 cw(c56.007,78.588) 47.947,94.458 49.502,98.383 ; 49.507,98.388 62.507,98.388 ; 62.512,98.373 64.067,94.458 ; 64.087,94.448 cw(c56.007,78.588) 73.092,83.583

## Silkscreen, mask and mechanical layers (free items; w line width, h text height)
Bottom Overlay:
  drawing of 17164 lines, arcs and shapes, not listed
  text "上知物理" at 59.942,60.369 h2.03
